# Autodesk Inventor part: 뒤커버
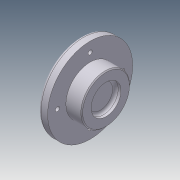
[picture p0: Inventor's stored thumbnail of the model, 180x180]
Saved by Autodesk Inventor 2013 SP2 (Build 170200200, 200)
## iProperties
Company: 한국ATC센터
Created: 2014-11
Part Number: 뒤커버
Document SubType Name: Modeling
Designer: KYOUNG IL JANG
Density: 2.71 g/cm^3
Material: 알루미늄-6061
Mass: 280.898 g
Surface Area: 198.677 cm^2
Volume: 103.653 cm^3
Author: KYOUNG IL JANG
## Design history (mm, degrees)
sketch "스케치1"
  geometry: L1 (-13.5, 0)-(13.5, 0); L2 (-13.5, 0)-(-13.5, 45.5); L3 (-13.5, 45.5)-(-3.5, 45.5); L4 (-3.5, 45.5)-(-3.5, 26); L5 (-3.5, 26)-(13.5, 26); L6 (13.5, 26)-(13.5, 0); 2 further points
  constraints: 12 end point, 3 parallel, 2 perpendicular, 1 coincident, 1 horizontal, 1 midpoint
  dimensions: "d0" = 27 distance of L1.start L1.end; "d1" = 91 diameter of L3 L1; "d2" = 52 diameter of L5 L1; "d3" = 10 distance of L2.end L3.end
revolve "회전1" sketch "스케치1" stored, may be unused: angle "d4" = 90 deg
sketch "스케치2"
  geometry: 2 further points
  constraints: 1 vertical alignment
  dimensions: "d14" = 35 distance of point (0, 0) point (0, 35)
hole "구멍2" sketch "스케치2" at (0, 35) diameter "d15" = 4.5; stored, may be unused: countersink angle "d19" = 90 deg, drill point angle "d21" = 118 deg; dims "d16" = 6, "d17" = 8, "d18" = 4.4, "d20" = 8
fillet "모깎기1" dims "d29" = 3
chamfer "모따기2" distance "d30" = 1; stored, may be unused: second distance "d31" = 2, angle "d32" = 30 deg
sketch "스케치3"
  geometry: L1 (-22.444, 6.652)-(-10, 14.967); L2 (-22.444, -6.652)-(-10, -14.967); L3 (10, -14.967)-(22.444, -6.652); L4 (22.444, 6.652)-(10, 14.967); A1 r 18 centre (0, 0) between (-18, 0) and (18, 0); A2 r 8 centre (18, 0) between (22.444, -6.652) and (22.444, 6.652); A3 r 8 centre (-18, 0) between (-22.444, 6.652) and (-22.444, -6.652); 1 further point
  constraints: 10 point on circle, 8 end point, 6 tangent, 3 centre point, 2 horizontal alignment, 2 parallel, 1 coincident, 1 equal radius
  dimensions: "d36" = 36 diameter of A1; "d37" = 16 diameter of A2
extrude "돌출1" join sketch "스케치3" distance "d38" = 7; taper "d39" = 0 deg
hole "구멍3" diameter "d43" = 32; stored, may be unused: countersink angle "d47" = 90 deg, drill point angle "d49" = 0 deg; dims "d41" = 10, "d42" = 10, "d44" = 6, "d45" = 4, "d46" = 2, "d48" = 6
fillet "모깎기2" dims "d40" = 3
node "솔리드1"
pattern_circular "원형 패턴2" dims angle "d34" = 360 deg
